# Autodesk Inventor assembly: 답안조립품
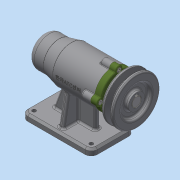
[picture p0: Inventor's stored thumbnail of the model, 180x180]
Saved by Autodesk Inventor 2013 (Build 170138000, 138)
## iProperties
Created: 2019-07
Part Number: 답안조립품
Document SubType Name: Assembly
Designer: dgall
Author: dgall
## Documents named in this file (12)
- C:\Users\dgall\Desktop\490704V1039\답안조립품.iam
- C:\Users\dgall\Desktop\490704V1039\V벨트풀리.ipt
- C:\Users\dgall\Desktop\490704V1039\멈춤나사 M3.ipt
- C:\Users\dgall\Desktop\490704V1039\베어링 6004.ipt
- C:\Users\dgall\Desktop\490704V1039\베어링 51202.ipt
- C:\Users\dgall\Desktop\490704V1039\본체.ipt
- C:\Users\dgall\Desktop\490704V1039\볼트 M4.ipt
- C:\Users\dgall\Desktop\490704V1039\어댑터슬리브.ipt
- C:\Users\dgall\Desktop\490704V1039\오일 실.ipt
- C:\Users\dgall\Desktop\490704V1039\축.ipt
- C:\Users\dgall\Desktop\490704V1039\커버.ipt
- C:\Users\dgall\Desktop\490704V1039\키 5 x 5 x 16.ipt
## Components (1 placed, 1 different names)
1. V벨트풀리:1 — 각도:11
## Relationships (1: Angle 1)
- 각도:11 [Angle]: V벨트풀리:1
